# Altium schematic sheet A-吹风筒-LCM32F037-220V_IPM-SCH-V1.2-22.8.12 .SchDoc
size A3; SheetNumber: 1; SheetTotal: 1
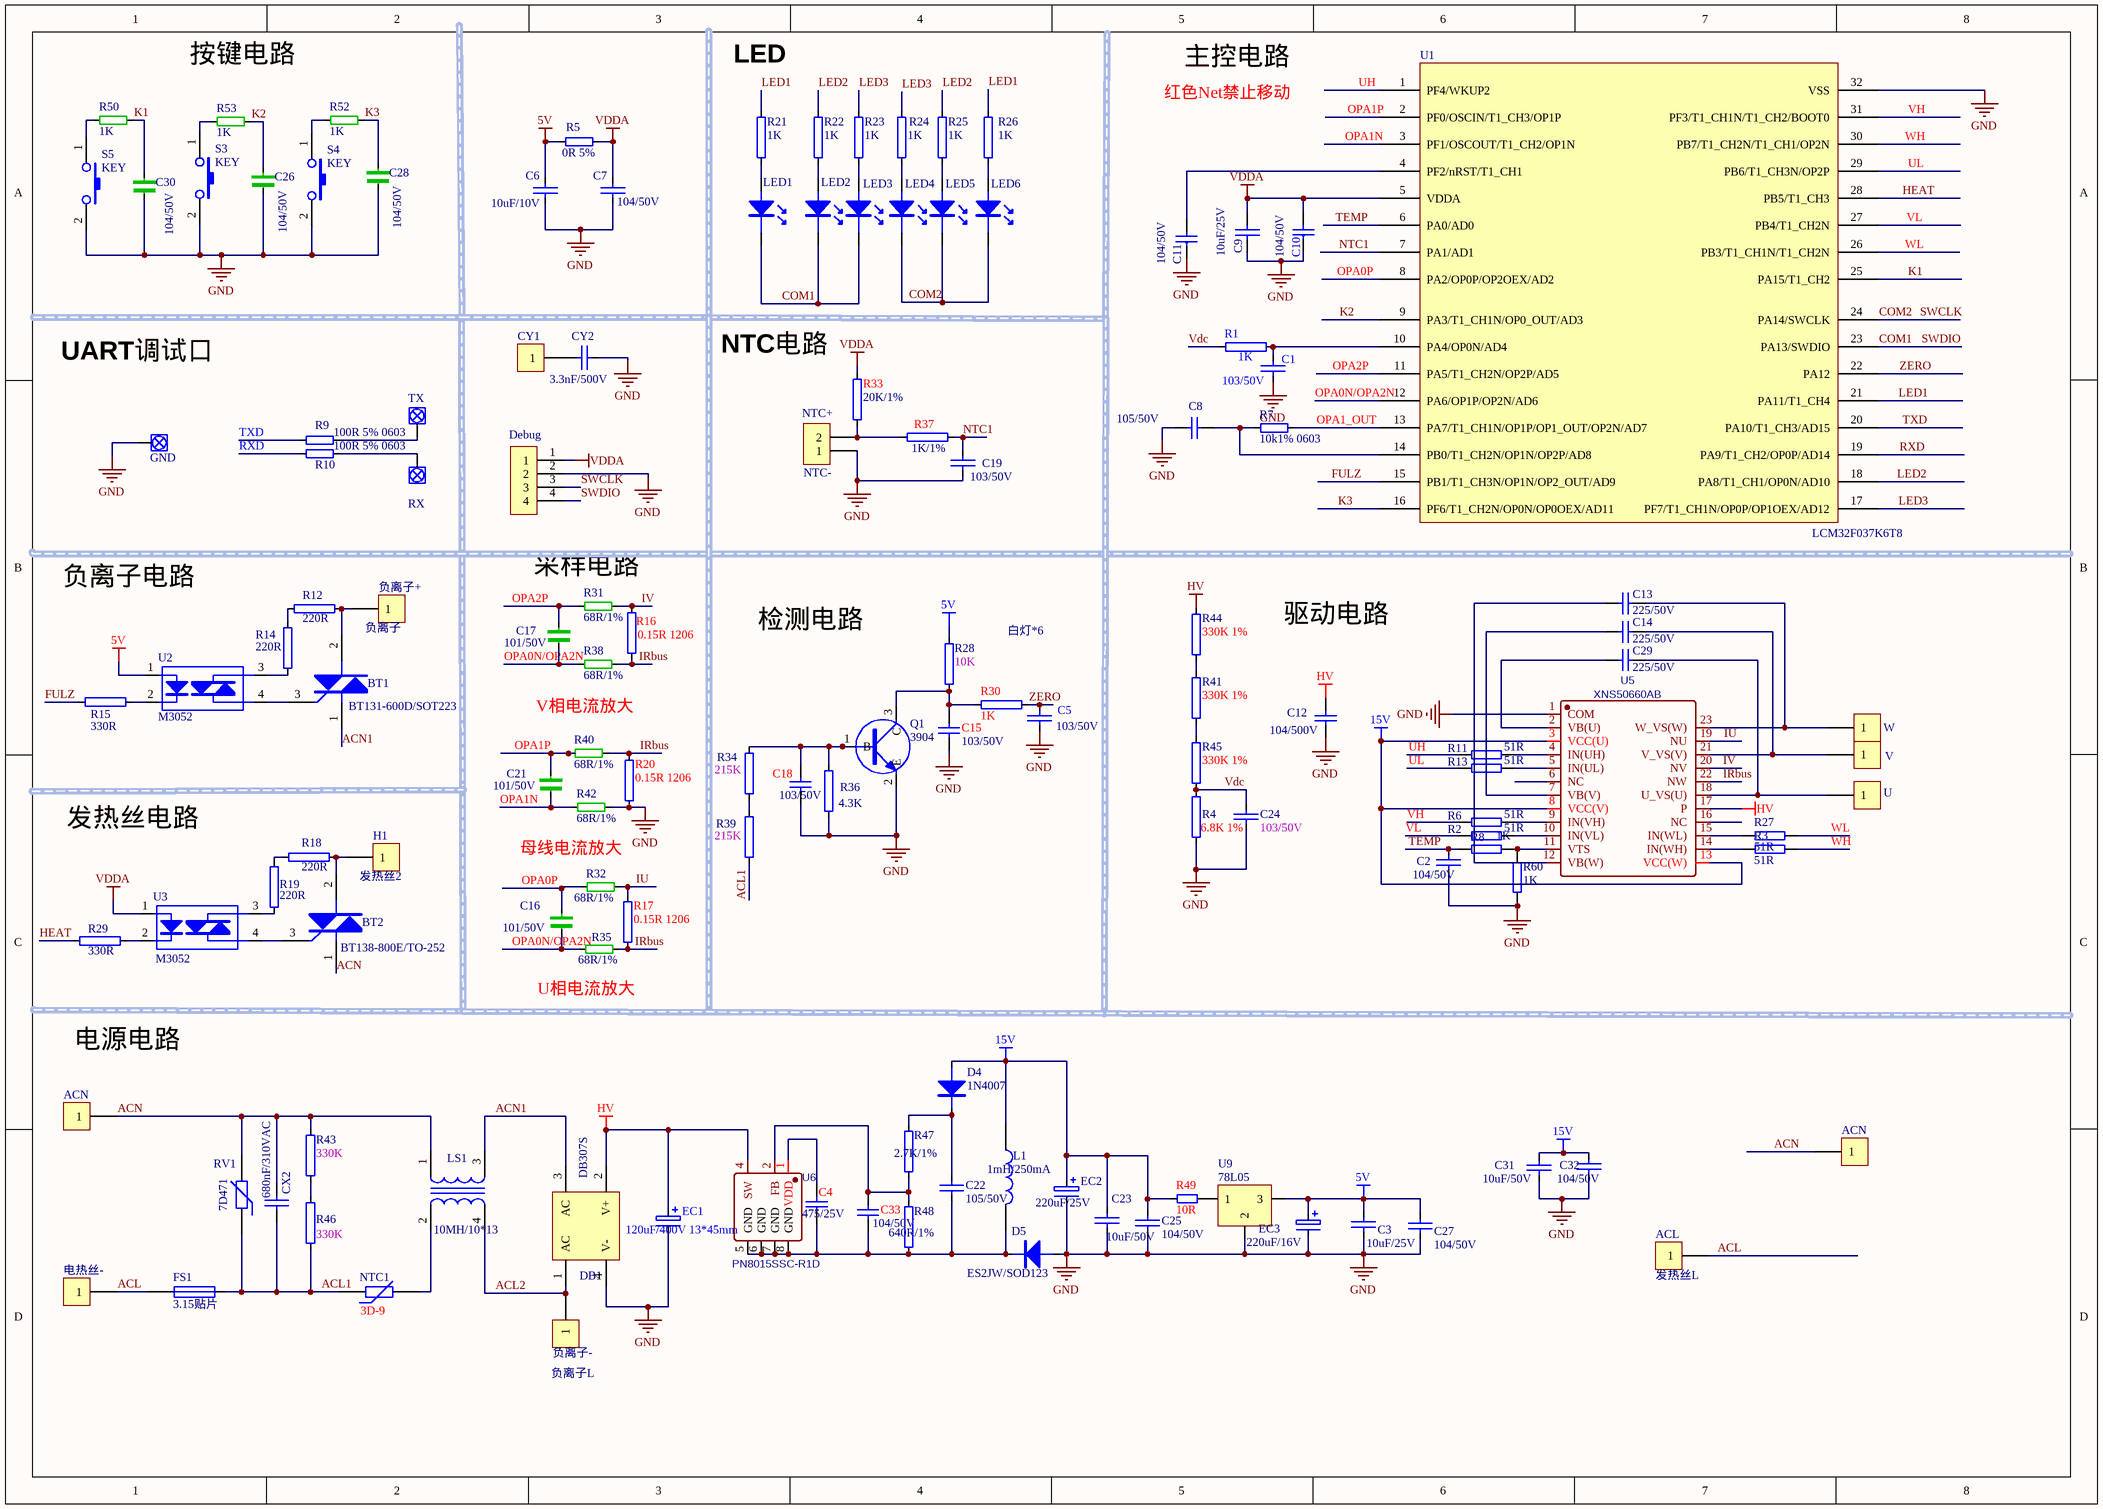
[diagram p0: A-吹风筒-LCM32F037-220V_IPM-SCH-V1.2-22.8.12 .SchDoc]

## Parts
(Parts that share a designator on the sheet are numbered #1, #2 ... from top to bottom, then left to right.)
ACL  发热丝L  [TP1.6]
ACN#1  (no value)  [TP1.6]
ACN#2  (no value)  [TP1.6]
BT1  BT131-600D/SOT223  [SOT-223-3_L6.5-W3.4-P2.30-LS7.0-BR]
BT2  BT138-800E/TO-252  [TO-252]
C1  103/50V  [0603C]
C2  104/50V  [0603C]
C3  10uF/25V  [0603C]
C4  475/25V  [C1206C]
C5  103/50V  [0603C]
C6  10uF/10V  [0805C]
C7  104/50V  [0603C]
C8  105/50V  [0603C]
C9  10uF/25V  [0805C]
C10  104/50V  [0603C]
C11  104/50V  [0603C]
C12  104/500V  [CAP7.5]
C13  225/50V  [C1206C]
C14  225/50V  [C1206C]
C15  103/50V  [0603C]
C16  101/50V  [0603C]
C17  101/50V  [0603C]
C18  103/50V  [0603C]
C19  103/50V  [0603C]
C21  101/50V  [0603C]
C22  105/50V  [0603C]
C23  10uF/50V  [0805C]
C24  103/50V  [0603C]
C25  104/50V  [0603C]
C26  104/50V  [0603C]
C27  104/50V  [0603C]
C28  104/50V  [0603C]
C29  225/50V  [C1206C]
C30  104/50V  [0603C]
C31  10uF/50V  [0603C]
C32  104/50V  [0603C]
C33  104/50V  [0603C]
CX2  680nF/310VAC  [CX0.58UF280VAC-18*9*15-H]
CY1  (no value)  [TP1.6 - 1]
CY2  3.3nF/500V  [C1206C]
D4  1N4007  [D-SOD-123]
D5  ES2JW/SOD123  [D-SOD-123]
DB1  DB307S  [DBG-DB107G-SMD]
Debug  CON4  [CN4P1.5-]  (value not drawn)
EC1  120uF/400V 13*45mm  [120UF/400V D18.3*H51.2]
EC2  220uF/25V  [ECT6.3_5.5]
EC3  220uF/16V  [ECT6.3_5.5]
FS1  3.15贴片  [FU 6*2.5]
GND  P  [P]  (value not drawn)
H1  发热丝2  [TP1.6]
L1  1mH/250mA  [LD7*7-SMD]
LED1  LED  [LED0603S]  (value not drawn)
LED2  LED  [LED0603S]  (value not drawn)
LED3  LED  [LED0603S]  (value not drawn)
LED4  LED  [LED0603S]  (value not drawn)
LED5  LED  [LED0603S]  (value not drawn)
LED6  LED  [LED0603S]  (value not drawn)
LS1  10MH/10*13  [LF-UU9.8 - 1]
NTC1  3D-9  [CYNTC-P10-S]
Q1  3904  [SOT23SDG-S]
R1  1K  [0603R]
R2  51R  [0603R]
R3  51R  [0603R]
R4  6.8K 1%  [0603R]
R5  0R 5%  [0603R]
R6  51R  [0603R]
R7  10k1% 0603  [R0603R]
R8  1K  [0603R]
R9  100R 5% 0603  [R0603R]
R10  100R 5% 0603  [R0603R]
R11  51R  [0603R]
R12  220R  [1206R]
R13  51R  [0603R]
R14  220R  [1206R]
R15  330R  [0603R]
R16  0.15R 1206  [1206R]
R17  0.15R 1206  [1206R]
R18  220R  [1206R]
R19  220R  [1206R]
R20  0.15R 1206  [1206R]
R21  1K  [0603R]
R22  1K  [0603R]
R23  1K  [0603R]
R24  1K  [0603R]
R25  1K  [0603R]
R26  1K  [0603R]
R27  51R  [0603R]
R28  10K  [0603R]
R29  330R  [0603R]
R30  1K  [0603R]
R31  68R/1%  [R0603R]
R32  68R/1%  [R0603R]
R33  20K/1%  [0603R]
R34  215K  [1206R]
R35  68R/1%  [R0603R]
R36  4.3K  [0603R]
R37  1K/1%  [0603R]
R38  68R/1%  [R0603R]
R39  215K  [1206R]
R40  68R/1%  [R0603R]
R41  330K 1%  [1206R]
R42  68R/1%  [R0603R]
R43  330K  [1206R]
R44  330K 1%  [1206R]
R45  330K 1%  [1206R]
R46  330K  [1206R]
R47  2.7K/1%  [1206R]
R48  640R/1%  [1206R]
R49  10R  [R1206R]
R50  1K  [R0603R]
R52  1K  [R0603R]
R53  1K  [R0603R]
R60  1K  [R0603R]
RV1  7D471  [CY2A473J]
RX  P  [P]  (value not drawn)
S1  (no value)  [CN2P4]
S3  KEY  [K-3.5*6-SMD]
S4  KEY  [K-3.5*6-SMD]
S5  KEY  [K-3.5*6-SMD]
TX  P  [P]  (value not drawn)
U  (no value)  [TP1.6-2.5*3.8]
U1  LCM32F037K6T8  [LQFP-32]
U2  M3052  [SO-4 - 1]
U3  M3052  [SO-4]
U5  XNS50660AB  [SOP23]
U6  PN8015SSC-R1D  [SOP-8_L4.9-W3.9-P1.27-LS6.0-BL-PE3]
U9  78L05  [78L05-SMD]
V  (no value)  [TP1.6-2.5*3.8]
W  (no value)  [TP1.6-2.5*3.8]
电热丝-  (no value)  [TP1.6]
负离子+  负离子  [TP1.6]
负离子-  (no value)  [TP1.6]

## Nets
5V: C3.1 C6.1 C27.1 EC3.1 R5.2 R28.1 U2.1(A) U9.3
15V: C23.1 C25.1 C31.1 C32.1 D4.1(A) EC2.1 L1.1 R49.1 U5.3(VCC(U)) U5.8(VCC(V)) U5.13(VCC(W))
GND: C1.1 C3.2 C5.2 C6.2 C7.2 C8.1 C9.2 C10.1 C11.1 C12.1 C15.2 C18.2 C19.1 C23.2 C24.2 C25.2 C26.2 C27.2 C28.2 C30.2 C31.2 C32.2 CY2.2 D5.1(A) DB1.4(V-) Debug.2 EC1.2 EC2.2 EC3.2 GND.1 Q1.2(E) R4.1 R20.1 R36.1 R42.1 S1.1 S3.2 S4.2 S5.2 U1.32(VSS) U5.1(COM) U9.2
HV: C12.2 DB1.2(V+) EC1.1 R44.2 U5.17(P) U6.4(SW)
VDDA: C7.1 C9.1 C10.2 Debug.1 R5.1 R33.2 U1.5(VDDA) U3.1(A)
ACL: ACL.1 FS1.1 电热丝-.1
ACL1: CX2.2 FS1.2 NTC1.1 R39.1 R46.2 RV1.1
ACL2: DB1.1(AC) LS1.4 负离子-.1
ACN: ACN#1.1 ACN#2.1 BT2.1(T) CX2.1 LS1.1 R43.1 RV1.2
ACN1: BT1.1(T) DB1.3(AC) LS1.3
COM1: Debug.4 LED1.2 LED2.2 LED3.2 U1.23(PA13/SWDIO)  [also labelled SWDIO]
COM2: Debug.3 LED4.2 LED5.2 LED6.2 U1.24(PA14/SWCLK)  [also labelled SWCLK]
FULZ: R15.1 U1.15(PB1/T1_CH3N/OP1N/OP2_OUT/AD9)
HEAT: R29.1 U1.28(PB5/T1_CH3)
IRbus: R16.2 R17.2 R20.2 R35.1 R38.1 R40.1 U5.22(NW)
IU: R17.1 R32.1 U5.19(NU)
IV: R16.1 R31.1 U5.20(NV)
K1: C30.1 R50.1 U1.25(PA15/T1_CH2)
K2: C26.1 R53.1 U1.9(PA3/T1_CH1N/OP0_OUT/AD3)
K3: C28.1 R52.1 U1.16(PF6/T1_CH2N/OP0N/OP0OEX/AD11)
LED1: R21.2 R26.2 U1.21(PA11/T1_CH4)
LED2: R22.2 R25.2 U1.18(PA8/T1_CH1/OP0N/AD10)
LED3: R23.2 R24.2 U1.17(PF7/T1_CH1N/OP0P/OP1OEX/AD12)
NTC1: C19.2 R37.2 U1.7(PA1/AD1)
OPA0N/OPA2N: C16.2 C17.2 R35.2 R38.2 U1.12(PA6/OP1P/OP2N/AD6)
OPA0P: C16.1 R32.2 U1.8(PA2/OP0P/OP2OEX/AD2)
OPA1_OUT: R7.1 U1.13(PA7/T1_CH1N/OP1P/OP1_OUT/OP2N/AD7)
OPA1N: C21.2 R42.2 U1.3(PF1/OSCOUT/T1_CH2/OP1N)
OPA1P: C21.1 R40.2 U1.2(PF0/OSCIN/T1_CH3/OP1P)
OPA2P: C17.1 R31.2 U1.11(PA5/T1_CH2N/OP2P/AD5)
RXD: R10.2 U1.19(PA9/T1_CH2/OP0P/AD14)
TEMP: C2.1 R8.2 U1.6(PA0/AD0)
TXD: R9.2 U1.20(PA10/T1_CH3/AD15)
UH: R11.2 U1.1(PF4/WKUP2)
UL: R13.2 U1.29(PB6/T1_CH3N/OP2P)
Vdc: C24.1 R1.1 R4.2 R45.1
VH: R6.2 U1.31(PF3/T1_CH1N/T1_CH2/BOOT0)
VL: R2.2 U1.27(PB4/T1_CH2N)
WH: R3.2 U1.30(PB7/T1_CH2N/T1_CH1/OP2N)
WL: R27.2 U1.26(PB3/T1_CH1N/T1_CH2N)
ZERO: C5.1 R30.2 U1.22(PA12)
NetBT1_2: BT1.2(T) R12.1 负离子+.1
NetBT1_3: BT1.3(G) U2.4(A/K)
NetBT2_2: BT2.2(T) H1.1 R18.1
NetBT2_3: BT2.3(G) U3.4(A/K)
NetC1_2: C1.2 R1.2 U1.10(PA4/OP0N/AD4)
NetC2_2: C2.2 R60.1
NetC4_1: C4.1 C22.2 C33.1 D5.2(K) L1.2 R48.1 U6.5(GND) U6.6(GND) U6.7(GND) U6.8(GND)
NetC4_2: C4.2 U6.1(VDD)
NetC8_2: C8.2 R7.2 U1.14(PB0/T1_CH2N/OP1N/OP2P/AD8)
NetC11_2: C11.2 U1.4(PF2/nRST/T1_CH1)
NetC13_1: C13.1 U5.12(VB(W))
NetC13_2: C13.2 U5.23(W_VS(W)) W.1
NetC14_1: C14.1 U5.7(VB(V))
NetC14_2: C14.2 U5.21(V_VS(V)) V.1
NetC15_1: C15.1 Q1.3(C) R28.2 R30.1
NetC18_1: C18.1 Q1.1(B) R34.2 R36.2
NetC22_1: C22.1 D4.2(K) R47.2
NetC29_1: C29.1 U5.2(VB(U))
NetC29_2: C29.2 U.1 U5.18(U_VS(U))
NetC33_2: C33.2 R47.1 R48.2 U6.2(FB)
NetCY1_1: CY1.1 CY2.1
NetLED1_1: LED1.1 R21.1
NetLED2_1: LED2.1 R22.1
NetLED3_1: LED3.1 R23.1
NetLED4_1: LED4.1 R24.1
NetLED5_1: LED5.1 R25.1
NetLED6_1: LED6.1 R26.1
NetLS1_2: LS1.2 NTC1.2
NetR2_1: R2.1 U5.10(IN(VL))
NetR3_1: R3.1 U5.14(IN(WH))
NetR6_1: R6.1 U5.9(IN(VH))
NetR8_1: R8.1 R60.2 U5.11(VTS)
NetR9_1: R9.1 TX.1
NetR10_1: R10.1 RX.1
NetR11_1: R11.1 U5.4(IN(UH))
NetR12_2: R12.2 R14.1
NetR13_1: R13.1 U5.5(IN(UL))
NetR14_2: R14.2 U2.3(A/K)
NetR15_2: R15.2 U2.2(K)
NetR18_2: R18.2 R19.1
NetR19_2: R19.2 U3.3(A/K)
NetR27_1: R27.1 U5.15(IN(WL))
NetR29_2: R29.2 U3.2(K)
NetR33_1: R33.1 R37.1 S1.2
NetR34_1: R34.1 R39.2
NetR41_1: R41.1 R45.2
NetR41_2: R41.2 R44.1
NetR43_2: R43.2 R46.1
NetR49_2: R49.2 U9.1
NetR50_2: R50.2 S5.1
NetR52_2: R52.2 S4.1
NetR53_2: R53.2 S3.1

Not connected (* = marked no-connect by the designer): U5 6(NC) 16(NC)

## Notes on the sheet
- 按键电路
- LED
- 主控电路
- 红色Net禁止移动
- UART调试口
- NTC电路
- (near S1) NTC+
- (near S1) NTC-
- 负离子电路
- (near R31) 采样电路
- 检测电路
- 白灯*6
- 驱动电路
- V相电流放大
- 发热丝电路
- 母线电流放大
- 电源电路
- (near R35) U相电流放大
- (near 负离子-) 负离子L
- Labels drawn without touching a wire or pin: GND

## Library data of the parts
ACL ACN#1 ACN#2 CY1 H1 U V W 电热丝- 负离子+ = CON1: Connector
BT1 BT2 = TRIAC
C1-C3 C5-C7 C10 C11 C19 C22-C25 C27 C31 C32 CY2 = CAP
C4 C33 = Cap: Capacitor
C8 = CAP: Capacitor; Value: 104/50V
C9 CX2 = CAP: Capacitor
C12 = Cap: Capacitor; Value: 104P/1KV
C13 C14 C29 = Cap: Value: 100pF
C15 C18 = Cap
C16 C17 C21 C26 C28 C30 = C_SMD: 贴片 无极性电容
D4 D5 = DIODE
DB1 = BRIDGE2: Diode Bridge
EC1-EC3 = ELE
FS1 = Fuse 1: Fuse
L1 = INDUCTOR
LS1 = TRANS1: 8MH
NTC1 RV1 = Res Varistor: Varistor (Voltage-Sensitive Resistor)
Q1 = NPN/SOT-89/BCE
R1 R4 R12 R14-R26 R28-R30 R33 R34 R36 R37 R39 R41 R43-R49 = RES2
R2 R3 R6 R8 R11 R13 R27 R60 = RES1
R5 R7 R9 R10 = RES
R31 R32 R35 R38 R40 R42 R50 R52 R53 = R_SMD: 贴片 电阻器
S1 = CON2: Connector
S3-S5 = SW
U2 U3 = OPTOTRIAC
U5 = XNS50660AB: BOM_Manufacturer: XINER; Contributor: LCSC
U6 = PN8015SSC-R1D: BOM_Manufacturer: chipown(芯朋微电子); Contributor: lcsc
负离子- = CON1: 负离子L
